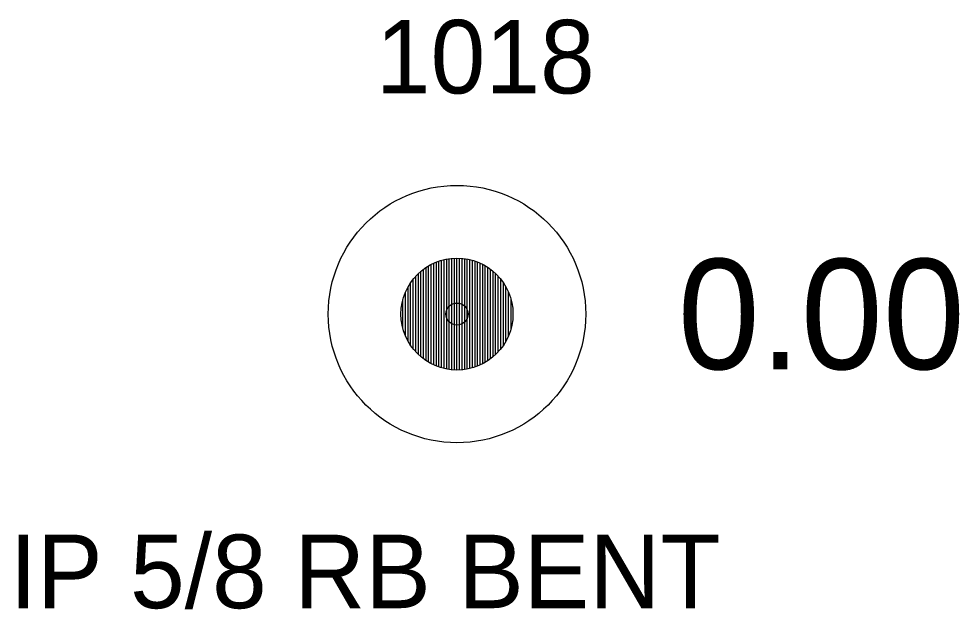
# Model space of a CAD drawing. Extents: x 1664393 to 1667175, y 987029 to 988607.
# Drawn here: x 1666547.43 to 1666560.21, y 987703.65 to 987711.68 of the extents above; entities that cross this region are included whole.
import ezdxf

# ---------------------------------------------------------------- set-up
doc = ezdxf.new("R2010")
doc.units = 0
for name, color, linetype in [('RD_EX_DV_Prop_txCode', 7, 'Continuous'), ('RD_EX_DV_PropPin', 7, 'Continuous'), ('RD_EX_TX_DV_Prop_ELEV', 7, 'Continuous'), ('RD_SMD_Locator', 7, 'Continuous')]:
    doc.layers.add(name, color=color, linetype=linetype)

msp = doc.modelspace()

# ---------------------------------------------------------------- linework, layer by layer
at = {"layer": 'RD_EX_DV_PropPin'}
for p, q in [((1666553.142, 987706.944), (1666553.142, 987708.385)), ((1666553.177, 987706.933), (1666553.177, 987708.396)), ((1666553.212, 987706.924), (1666553.212, 987708.405)), ((1666553.247, 987706.916), (1666553.247, 987708.412)), ((1666553.282, 987706.911), (1666553.282, 987708.418)), ((1666553.317, 987706.907), (1666553.317, 987708.422)), ((1666553.352, 987706.904), (1666553.352, 987708.425)), ((1666553.387, 987706.903), (1666553.387, 987708.425)), ((1666553.422, 987706.904), (1666553.422, 987708.425)), ((1666553.457, 987706.907), (1666553.457, 987708.422)), ((1666553.492, 987706.911), (1666553.492, 987708.418)), ((1666553.527, 987706.916), (1666553.527, 987708.412)), ((1666553.562, 987706.924), (1666553.562, 987708.405)), ((1666553.597, 987706.933), (1666553.597, 987708.396)), ((1666553.632, 987706.944), (1666553.632, 987708.385)), ((1666552.932, 987707.054), (1666552.932, 987708.274)), ((1666552.967, 987707.03), (1666552.967, 987708.299)), ((1666553.002, 987707.008), (1666553.002, 987708.321)), ((1666553.037, 987706.989), (1666553.037, 987708.34)), ((1666553.072, 987706.972), (1666553.072, 987708.357)), ((1666553.107, 987706.957), (1666553.107, 987708.372)), ((1666553.667, 987706.957), (1666553.667, 987708.372)), ((1666553.702, 987706.972), (1666553.702, 987708.357)), ((1666553.737, 987706.989), (1666553.737, 987708.34)), ((1666553.772, 987707.008), (1666553.772, 987708.321)), ((1666553.807, 987707.03), (1666553.807, 987708.299)), ((1666553.842, 987707.054), (1666553.842, 987708.274)), ((1666552.792, 987707.19), (1666552.792, 987708.138)), ((1666552.827, 987707.149), (1666552.827, 987708.179)), ((1666552.862, 987707.114), (1666552.862, 987708.215)), ((1666552.897, 987707.082), (1666552.897, 987708.246)), ((1666553.877, 987707.082), (1666553.877, 987708.246)), ((1666553.912, 987707.114), (1666553.912, 987708.215)), ((1666553.947, 987707.149), (1666553.947, 987708.179)), ((1666553.982, 987707.19), (1666553.982, 987708.138)), ((1666552.722, 987707.295), (1666552.722, 987708.034)), ((1666552.757, 987707.238), (1666552.757, 987708.091)), ((1666554.017, 987707.238), (1666554.017, 987708.091)), ((1666554.052, 987707.295), (1666554.052, 987708.034)), ((1666552.687, 987707.366), (1666552.687, 987707.962)), ((1666554.087, 987707.366), (1666554.087, 987707.962)), ((1666552.652, 987707.468), (1666552.652, 987707.86)), ((1666554.122, 987707.468), (1666554.122, 987707.86))]:
    msp.add_line(p, q, dxfattribs=at)
for radius in [1.75, 0.761]:
    msp.add_circle((1666553.387, 987707.664), radius, dxfattribs=at)
at = {"layer": 'RD_SMD_Locator'}
msp.add_circle((1666553.387, 987707.664), 0.15, dxfattribs=at)

# ---------------------------------------------------------------- texts
at = {"layer": 'RD_EX_DV_Prop_txCode'}
for s, p in [('1018', (1666552.285, 987710.664)), ('IP 5/8 RB BENT', (1666547.308, 987703.664))]:
    msp.add_text(s, height=1, dxfattribs=at).set_placement(p)
at = {"layer": 'RD_EX_TX_DV_Prop_ELEV'}
msp.add_text('0.00', height=1.5, dxfattribs=at).set_placement((1666556.387, 987706.914))

doc.saveas('drawing.dxf')
